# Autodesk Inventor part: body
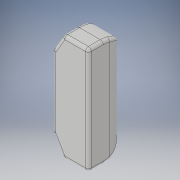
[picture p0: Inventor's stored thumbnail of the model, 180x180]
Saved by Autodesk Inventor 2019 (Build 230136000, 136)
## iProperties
Created: 2020-08
Part Number: body
Material: 一般
Document SubType Name: Modeling
Designer: kikut
Density: 1 g/cm^3
Appearance: 既定
Author: kikut
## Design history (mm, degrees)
sketch "スケッチ1"
  geometry: L1 (-0.06, -0.18)-(0.06, -0.18); L2 (0.06, -0.18)-(0.06, 0.18); L3 (0.06, 0.18)-(-0.06, 0.18); L4 (-0.06, 0.18)-(-0.06, -0.18); L5 (-0.06, -0.18)-(0.06, 0.18); L6 (0.06, -0.18)-(-0.06, 0.18); 1 further point
  constraints: 12 end point, 2 midpoint, 2 parallel, 1 horizontal, 1 perpendicular
  dimensions: "d0" = 0.36 distance of L1.end L2.end; "d1" = 0.12 distance of L2.end L3.end
extrude "押し出し1" new body sketch "スケッチ1" distance "d2" = 0.06; taper "d4" = 0 deg; dims "d3" = 0.07, "d5" = 0
fillet "フィレット2" dims "d7" = 0.08
sketch "スケッチ2"
  geometry: L1 (0.12, -0.05)-(0.12, -0.13) reference; L2 (0.12, -0.07)-(0.14, -0.07); L3 (0.14, -0.07)-(0.14, -0.17); L4 (0.14, -0.17)-(-0.02, -0.17); L5 (-0.02, -0.17)-(-0.02, -0.07); L6 (-0.02, -0.07)-(0, -0.07); L7 (0, 0)-(0.12, 0) reference; A1 r 0.06 centre (0.06, -0.07) between (0, -0.07) and (0.12, -0.07); 1 further point
  constraints: 10 end point, 4 perpendicular, 2 point on circle, 2 point on line, 1 centre point, 1 horizontal
  dimensions: "d8" = 0.06 radius of A1; "d9" = 0.02 distance of L5.end L6.end; "d10" = 0.02 distance of L2.start L2.end; "d11" = 0.16 distance of L3.end L4.end; "d12" = 0.1 distance of L2.end L3.end; "d13" = 0.13 dimension on A1 L7
extrude "押し出し2" cut sketch "スケッチ2" extent not by distance; stored distance "d14" = 0.06; taper "d15" = 0 deg
sketch "スケッチ3"
  geometry: L1 (-0.06, 0.2)-(-0.014, 0.2); L2 (-0.014, 0.2)-(-0.06, 0.12); L3 (-0.06, 0.12)-(-0.06, 0.2); L4 (-0.2, 0)-(0.104, 0) reference; L5 (0, -0.256)-(0, 0.278) reference; L6 (-0.06, -0.12)-(-0.06, -0.2); L7 (-0.06, -0.2)-(-0.014, -0.2); L8 (-0.014, -0.2)-(-0.06, -0.12); 1 further point
  constraints: 12 end point, 2 perpendicular, 1 horizontal, 1 vertical
  dimensions: "d18" = 60 deg angle of L2 L4; "d19" = 0.06 distance between parallel lines of L5 L3; "d21" = 0.12 distance from line of L2.end L4; "d22" = 0.08 distance of L2.end L1.start; "d23" = 30 deg angle of L8 L6; "d24" = 0.12 distance from line of L6.start L4; "d25" = 0.08 distance of L6.start L6.end; "d26" = 0.06 distance between parallel lines of L5 L6
extrude "押し出し3" cut sketch "スケッチ3" distance "d27" = 10; taper "d28" = 0 deg
fillet "フィレット5" dims "d29" = 0.01
node "ソリッド1"
